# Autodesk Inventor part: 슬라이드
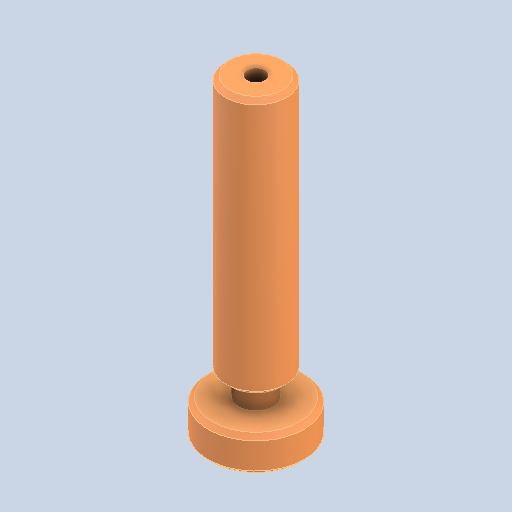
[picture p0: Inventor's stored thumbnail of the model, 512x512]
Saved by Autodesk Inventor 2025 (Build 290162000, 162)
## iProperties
Created: 2024-07
Part Number: 슬라이드
Material: 강철, 연강
Document SubType Name: Modeling
Designer: samsung
Density: 7.86 g/cm^3
Appearance: 기본값
Author: jhkim
Sending System: Autodesk Inventor 2025
Preprocessor: ST-DEVELOPER v20
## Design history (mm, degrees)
feature "솔리드1"
node "솔리드2"
